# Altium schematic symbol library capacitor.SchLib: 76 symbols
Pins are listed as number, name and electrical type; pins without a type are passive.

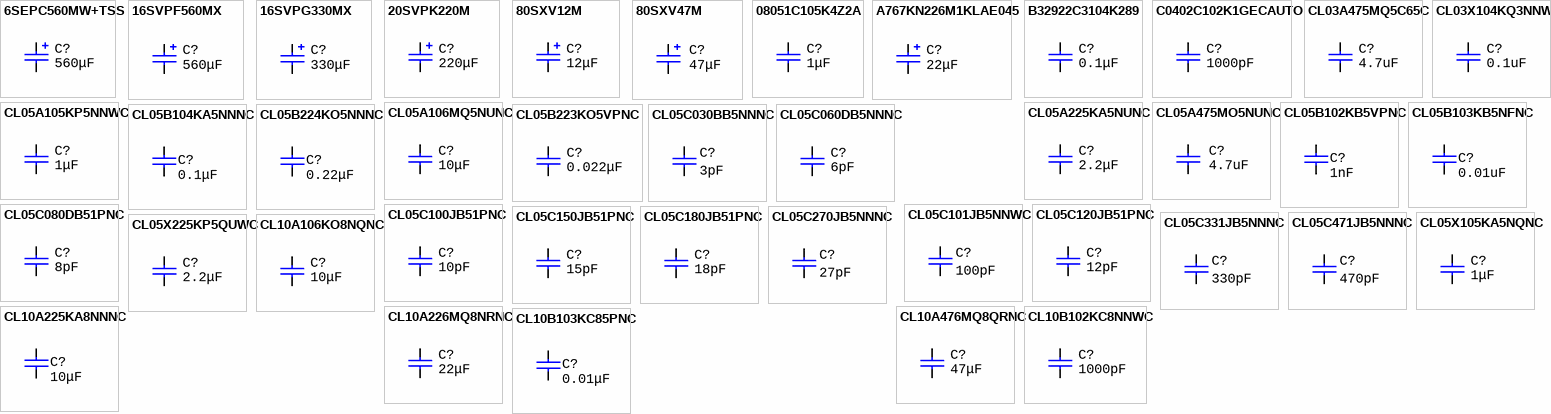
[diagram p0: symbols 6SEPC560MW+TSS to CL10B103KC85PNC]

## 6SEPC560MW+TSS
designator C?  value 560μF  (hidden comment: 6SEPC560MW+TSS)
560uF, 6.3V, D6.3C2.5H9, Polymer, ±20%, -55...+105°C; Manufacturer: Panasonic
footprint CAP: D6.3C2.5H9
pins: 1, 2

## 16SVPF560MX
designator C?  value 560μF  (hidden comment: 16SVPF560MX)
560uF, 16V, Polymer, ripple 3.9A, SMD D8AL10.5, ±20%, 18 mOhms, -55...+105°C; Manufacturer: Panasonic
footprint CAP: 16SVPF560MX (D8L10.5)
pins: 1, 2

## 16SVPG330MX
designator C?  value 330μF  (hidden comment: 16SVPG330MX)
330uF, 16V, Polymer, SMD D8AL6.9, ±20%, 16 mOhms, -55...+105°C; Manufacturer: Panasonic
footprint CAP: 16SVPG330MX
pins: 1, 2

## 20SVPK220M
designator C?  value 220μF  (hidden comment: 20SVPK220M)
220uF, 20V, Polymer, SMD D8AL6.9, ±20%, 25 mOhms, -55...+105°C; Manufacturer: Panasonic
footprint CAP: 16SVPG330MX
pins: 1, 2

## 80SXV12M
designator C?  value 12μF  (hidden comment: 80SXV12M)
12uF, 80V, Polymer, SMD D8AL6.9, ±20%, 60 mOhms, -55...+105°C; Manufacturer: Panasonic
footprint CAP: 16SVPG330MX
pins: 1, 2

## 80SXV47M
designator C?  value 47μF  (hidden comment: 80SXV47M)
47uF, 80V, 3.1A ripple, SMD D10A10.3H12.6C11, Polymer, ±20%, -55...+125°C; Manufacturer: Panasonic
footprint CAP: D10A10.3H12.6C11 (SMD Capacitor)
pins: 1, 2

## 08051C105K4Z2A
designator C?  value 1μF  (hidden comment: 08051C105K4Z2A)
1uF, 100V, 0805, X7R, ±10%, -55...+125°C; Manufacturer: Kyocera AVX
footprint CAP: 0805
pins: 1, 2

## A767KN226M1KLAE045
designator C?  value 22μF  (hidden comment: A767KN226M1KLAE045)
22uF, 80V, Polymer, ripple 2.1A, SMD D8AL10.5, ±20%, 45 mOhms, -55...+105°C; Manufacturer: Kemet
footprint CAP: 16SVPF560MX (D8L10.5)
pins: 1, 2

## B32922C3104K289
designator C?  value 0.1μF  (hidden comment: B32922C3104K289)
0.1uF, 630VDC, L18W5H15, Film, ±10%, -55...+125°C; Manufacturer: Epcos; Manufacturer: TDK EPCOS
footprint CAP: B32922 (18x5x15 mm)
pins: 1, 2

## C0402C102K1GECAUTO
designator C?  value 1000pF  (hidden comment: C0402C102K1GECAUTO)
1000pF, 100V, 0402, NPO, ±10%, -55...+125°C; Manufacturer: Kemet
footprint CAP: 0402
pins: 1, 2

## CL03A475MQ5C65C
designator C?  value 4.7uF  (hidden comment: CL03A475MQ5C65C)
4.7uF, 6.3V, 0201, X5R, ±20%, -55...+85°C; Manufacturer: Murata; Manufacturer: Samsung
footprint CAP: 0201
pins: 1, 2

## CL03X104KQ3NNWC
designator C?  value 0.1uF  (hidden comment: CL03X104KQ3NNWC)
0.1uF, 6.3V, 0201, X6S, ±20%, -55...+105°C; Manufacturer: Samsung
footprint CAP: 0201
pins: 1, 2

## CL05A105KP5NNWC
designator C?  value 1μF  (hidden comment: CL05A105KP5NNWC)
1uF, 10V, 0402, X5R, ±10%, -55...+125°C; Manufacturer: Samsung
footprint CAP: 0402
pins: 1, 2

## CL05A106MQ5NUNC
designator C?  value 10μF  (hidden comment: CL05A106MQ5NUNC)
10uF, 6.3V, 0402, X5R, ±10%, -55...+85°C; Manufacturer: Samsung
footprint CAP: 0402
pins: 1, 2

## CL05A225KA5NUNC
designator C?  value 2.2μF  (hidden comment: CL05A225KA5NUNC)
2.2uF, 25V, 0402, X5R, ±10%, -55...+85°C; Manufacturer: Samsung
footprint CAP: 0402
pins: 1, 2

## CL05A475MO5NUNC
designator C?  value 4.7uF  (hidden comment: CL05A475MO5NUNC)
4.7uF, 16V, 0402, X5R, ±20%, -55...+85°C; Manufacturer: Samsung
footprint CAP: 0402
pins: 1, 2

## CL05B102KB5VPNC
designator C?  value 1nF  (hidden comment: CL05B102KB5VPNC)
1nF, 50V, 0402, X7R, ±10%, -55...+125°C; Manufacturer: Samsung
footprint CAP: 0402
pins: 1, 2

## CL05B103KB5NFNC
designator C?  value 0.01uF  (hidden comment: CL05B103KB5NFNC)
0.01uF, 50V, 0402, X7R, ±10%, -55...+125°C; Manufacturer: Samsung
footprint CAP: 0402
pins: 1, 2

## CL05B104KA5NNNC
designator C?  value 0.1μF  (hidden comment: CL05B104KA5NNNC)
0.1uF, 25V, 0402, X7R, ±10%, -55...+125°C; Manufacturer: Samsung
footprint CAP: 0402
pins: 1, 2

## CL05B223KO5VPNC
designator C?  value 0.022μF  (hidden comment: CL05B223KO5VPNC)
0.022uF, 16V, 0402, X7R, ±10%, -55...+125°C; Manufacturer: Samsung
footprint CAP: 0402
pins: 1, 2

## CL05B224KO5NNNC
designator C?  value 0.22μF  (hidden comment: CL05B224KO5NNNC)
0.22uF, 16V, 0402, X7R, ±10%, -55...+125°C; Manufacturer: Samsung
footprint CAP: 0402
pins: 1, 2

## CL05C030BB5NNNC
designator C?  value 3pF  (hidden comment: CL05C030BB5NNNC)
3pF, 50V, 0402, NPO, ±5%, -55...+125°C; Manufacturer: Samsung
footprint CAP: 0402
pins: 1, 2

## CL05C060DB5NNNC
designator C?  value 6pF  (hidden comment: CL05C060DB5NNNC)
6pF, 50V, 0402, C0G (NP0), ±0.5pF, -55...+125°C; Manufacturer: Samsung
footprint CAP: 0402
pins: 1, 2

## CL05C080DB51PNC
designator C?  value 8pF  (hidden comment: CL05C080DB51PNC)
8pF, 50V, 0402, C0G (NP0), ±5%, -55...+125°C; Manufacturer: Samsung
footprint CAP: 0402
pins: 1, 2

## CL05C100JB51PNC
designator C?  value 10pF  (hidden comment: CL05C100JB51PNC)
10pF, 50V, 0402, C0G (NP0), ±5%, -55...+125°C; Manufacturer: Samsung
footprint CAP: 0402
pins: 1, 2

## CL05C101JB5NNWC
designator C?  value 100pF  (hidden comment: CL05C101JB5NNWC)
100pF, 50V, 0402, C0G (NP0), ±5%, -55...+125°C; Manufacturer: Samsung
footprint CAP: 0402
pins: 1, 2

## CL05C120JB51PNC
designator C?  value 12pF  (hidden comment: CL05C120JB51PNC)
12pF, 50V, 0402, C0G (NP0), ±5%, -55...+125°C; Manufacturer: Samsung
footprint CAP: 0402
pins: 1, 2

## CL05C150JB51PNC
designator C?  value 15pF  (hidden comment: CL05C150JB51PNC)
15pF, 50V, 0402, C0G (NP0), ±5%, -55...+125°C; Manufacturer: Samsung
footprint CAP: 0402
pins: 1, 2

## CL05C180JB51PNC
designator C?  value 18pF  (hidden comment: CL05C180JB51PNC)
18pF, 50V, 0402, C0G (NP0), ±5%, -55...+125°C; Manufacturer: Samsung
footprint CAP: 0402
pins: 1, 2

## CL05C270JB5NNNC
designator C?  value 27pF  (hidden comment: CL05C270JB5NNNC)
27pF, 50V, 0402, C0G (NP0), ±5%, -55...+125°C; Manufacturer: Samsung
footprint CAP: 0402
pins: 1, 2

## CL05C331JB5NNNC
designator C?  value 330pF  (hidden comment: CL05C331JB5NNNC)
330pF, 50V, 0402, NPO, ±5%, -55...+125°C; Manufacturer: Samsung
footprint CAP: 0402
pins: 1, 2

## CL05C471JB5NNNC
designator C?  value 470pF  (hidden comment: CL05C471JB5NNNC)
470pF, 50V, 0402, NPO, ±5%, -55...+125°C; Manufacturer: Samsung
footprint CAP: 0402
pins: 1, 2

## CL05X105KA5NQNC
designator C?  value 1μF  (hidden comment: CL05X105KA5NQNC)
1uF, 25V, 0402, X6S, ±10%, -55...+105°C; Manufacturer: Samsung
footprint CAP: 0402
pins: 1, 2

## CL05X225KP5QUWC
designator C?  value 2.2μF  (hidden comment: CL05X225KP5QUWC)
2.2uF, 10V, 0402, X6S, ±10%, -55...+85°C; Manufacturer: Samsung
footprint CAP: 0402
pins: 1, 2

## CL10A106KO8NQNC
designator C?  value 10μF  (hidden comment: CL10A106KO8NQNC)
10uF, 16V, 0603, X7R, ±10%, -55...+85°C; Manufacturer: Samsung
footprint CAP: 0603
pins: 1, 2

## CL10A225KA8NNNC
designator C?  value 10μF  (hidden comment: CL10A225KA8NNNC)
10uF, 25V, 0603, X5R, ±10%, -55...+85°C; Manufacturer: Samsung
footprint CAP: 0603
pins: 1, 2

## CL10A226MQ8NRNC
designator C?  value 22μF  (hidden comment: CL10A226MQ8NRNC)
22uF, 6.3V, 0603, X7R, ±20%, -55...+85°C; Manufacturer: Samsung
footprint CAP: 0603
pins: 1, 2

## CL10A476MQ8QRNC
designator C?  value 47μF  (hidden comment: CL10A476MQ8QRNC)
47uF, 6.3V, 0603, X5R, ±20%, -55...+85°C; Manufacturer: Samsung
footprint CAP: 0603
pins: 1, 2

## CL10B102KC8NNWC
designator C?  value 1000pF  (hidden comment: CL10B102KC8NNWC)
1000pF, 100V, 0603, NPO, ±10%, -55...+125°C; Manufacturer: Samsung
footprint CAP: 0603
pins: 1, 2

## CL10B103KC85PNC
designator C?  value 0.01μF  (hidden comment: CL10B103KC85PNC)
0.01uF, 100V, 0603, X7R, ±10%, -55...+125°C; Manufacturer: Samsung
footprint CAP: 0603
pins: 1, 2

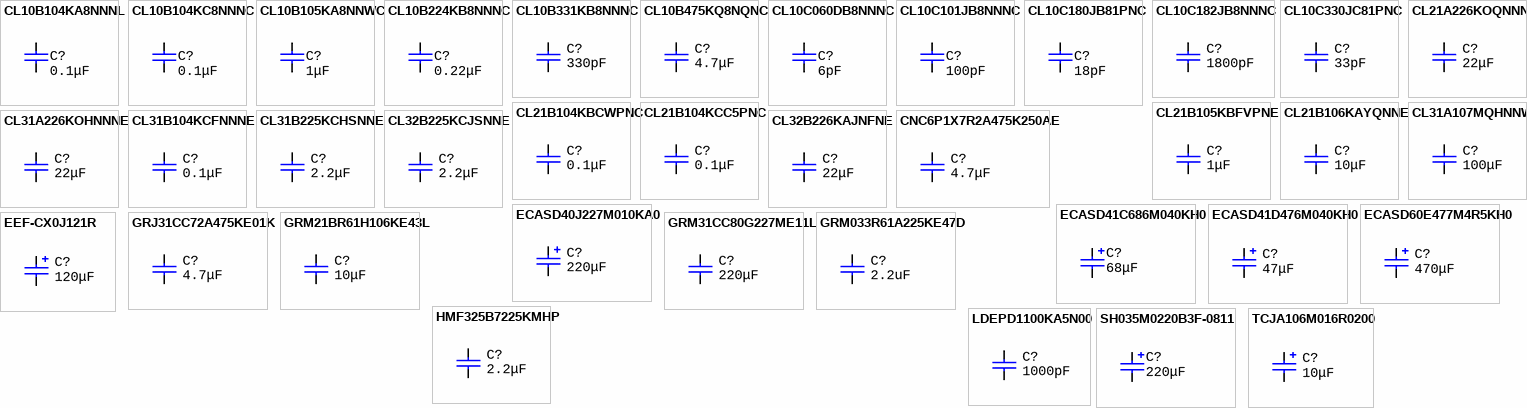
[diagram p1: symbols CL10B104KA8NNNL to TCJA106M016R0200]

## CL10B104KA8NNNL
designator C?  value 0.1μF  (hidden comment: CL10B104KA8NNNL)
0.1uF, 25V, 0603, X7R, ±10%, -55...+125°C; Manufacturer: Samsung
footprint CAP: 0603
pins: 1, 2

## CL10B104KC8NNNC
designator C?  value 0.1μF  (hidden comment: CL10B104KC8NNNC)
0.1uF, 100V, 0603, X7R, ±10%, -55...+125°C; Manufacturer: Samsung
footprint CAP: 0603
pins: 1, 2

## CL10B105KA8NNWC
designator C?  value 1μF  (hidden comment: CL10B105KA8NNWC)
1uF, 25V, 0603, X7R, ±10%, -55...+125°C; Manufacturer: Samsung
footprint CAP: 0603
pins: 1, 2

## CL10B224KB8NNNC
designator C?  value 0.22μF  (hidden comment: CL10B224KB8NNNC)
0.22uF, 50V, 0603, X7R, ±10%, -55...+125°C; Manufacturer: Samsung
footprint CAP: 0603
pins: 1, 2

## CL10B331KB8NNNC
designator C?  value 330pF  (hidden comment: CL10B331KB8NNNC)
330pF, 50V, 0603, X7R, ±10%, -55...+125°C; Manufacturer: Samsung
footprint CAP: 0603
pins: 1, 2

## CL10B475KQ8NQNC
designator C?  value 4.7μF  (hidden comment: CL10B475KQ8NQNC)
4.7uF, 6.3V, 0603, X7R, ±20%, -55...+85°C; Manufacturer: Samsung
footprint CAP: 0603
pins: 1, 2

## CL10C060DB8NNNC
designator C?  value 6pF  (hidden comment: CL10C060DB8NNNC)
6pF, 50V, 0603, C0G (NP0), ±10%, -55...+125°C; Manufacturer: Samsung
footprint CAP: 0603
pins: 1, 2

## CL10C101JB8NNNC
designator C?  value 100pF  (hidden comment: CL10C101JB8NNNC)
100pF, 50V, 0603, C0G (NP0), ±5%, -55...+125°C; Manufacturer: Samsung
footprint CAP: 0603
pins: 1, 2

## CL10C180JB81PNC
designator C?  value 18pF  (hidden comment: CL10C180JB81PNC)
18pF, 50V, 0603, C0G (NP0), ±5%, -55...+125°C; Manufacturer: Samsung
footprint CAP: 0603
pins: 1, 2

## CL10C182JB8NNNC
designator C?  value 1800pF  (hidden comment: CL10C182JB8NNNC)
1800pF, 50V, 0603, NPO, ±10%, -55...+125°C; Manufacturer: Samsung
footprint CAP: 0603
pins: 1, 2

## CL10C330JC81PNC
designator C?  value 33pF  (hidden comment: CL10C330JC81PNC)
33pF, 100V, 0603, NPO, ±10%, -55...+125°C; Manufacturer: Samsung
footprint CAP: 0603
pins: 1, 2

## CL21A226KOQNNNE
designator C?  value 22μF  (hidden comment: CL21A226KOQNNNE)
22uF, 16V, 0805, X7R, ±10%, -55...+125°C; Manufacturer: Samsung
footprint CAP: 0805
pins: 1, 2

## CL21B104KBCWPNC
designator C?  value 0.1μF  (hidden comment: CL21B104KBCWPNC)
0.1uF, 50V, 0805, X7R, ±10%, -55...+125°C; Manufacturer: Samsung
footprint CAP: 0805
pins: 1, 2

## CL21B104KCC5PNC
designator C?  value 0.1μF  (hidden comment: CL21B104KCC5PNC)
0.1uF, 100V, 0805, X7R, ±10%, -55...+125°C; Manufacturer: Samsung
footprint CAP: 0805
pins: 1, 2

## CL21B105KBFVPNE
designator C?  value 1μF  (hidden comment: CL21B105KBFVPNE)
1uF, 50V, 0805, X7R, ±10%, -55...+125°C; Manufacturer: Samsung
footprint CAP: 0805
pins: 1, 2

## CL21B106KAYQNNE
designator C?  value 10μF  (hidden comment: CL21B106KAYQNNE)
10uF, 25V, 0805, X7R, ±10%, -55...+125°C; Manufacturer: Samsung
footprint CAP: 0805
pins: 1, 2

## CL31A107MQHNNWE
designator C?  value 100μF  (hidden comment: CL31A107MQHNNWE)
100uF, 6.3V, 1206, X5R, ±20%, -55...+125°C; Manufacturer: Samsung
footprint CAP: 1206
pins: 1, 2

## CL31A226KOHNNNE
designator C?  value 22μF  (hidden comment: CL31A226KOHNNNE)
22uF, 16V, 1206, X5R, ±10%, -55...+125°C; Manufacturer: Samsung
footprint CAP: 1206
pins: 1, 2

## CL31B104KCFNNNE
designator C?  value 0.1μF  (hidden comment: CL31B104KCFNNNE)
0.1uF, 100V, 1206, X7R, ±10%, -55...+125°C; Manufacturer: Samsung
footprint CAP: 1206
pins: 1, 2

## CL31B225KCHSNNE
designator C?  value 2.2μF  (hidden comment: CL31B225KCHSNNE)
2.2uF, 100V, 1206, X7R, ±10%, -55...+125°C; Manufacturer: Samsung
footprint CAP: 1206
pins: 1, 2

## CL32B225KCJSNNE
designator C?  value 2.2μF  (hidden comment: CL32B225KCJSNNE)
2.2uF, 100V, 1210, X7R, ±10%, -55...+125°C; Manufacturer: Samsung
footprint CAP: 1210
pins: 1, 2

## CL32B226KAJNFNE
designator C?  value 22μF  (hidden comment: CL32B226KAJNFNE)
22uF, 25V, 1210, X5R, ±10%, -55...+125°C; PartNumber: CL32B105KCJSNNE; Manufacturer: Samsung
footprint CAP: 1210
pins: 1, 2

## CNC6P1X7R2A475K250AE
designator C?  value 4.7μF  (hidden comment: CNC6P1X7R2A475K250AE)
4.7uF, 100V, 1210, X7R, ±10%, -55...+125°C; Manufacturer: Samsung; Manufacturer: TDK
footprint CAP: 1210
pins: 1, 2

## ECASD40J227M010KA0
designator C?  value 220μF  (hidden comment: ECASD40J227M010KA0)
220uF, 6.3V, Type E (7343), ±10%, 10 mOhms, -55...+125°C; Manufacturer: Murata
footprint CAP: TANTAL-E (7343)
pins: 1, 2

## ECASD41C686M040KH0
designator C?  value 68μF  (hidden comment: ECASD41C686M040KH0)
68uF, 16V, Type E (7343), ±20%, 40 mOhms, -55...+125°C; Manufacturer: Murata; Manufacturer Part Number: ECASD41C685M070K00
footprint CAP: TANTAL-E (7343)
pins: 1, 2

## ECASD41D476M040KH0
designator C?  value 47μF  (hidden comment: ECASD41D476M040KH0)
47uF, 25V, Type E (7343), ±20%, 40 mOhms, -55...+125°C; Manufacturer: Murata
footprint CAP: TANTAL-E (7343)
pins: 1, 2

## ECASD60E477M4R5KH0
designator C?  value 470μF  (hidden comment: ECASD60E477M4R5KH0)
470uF, 2.5V, Type E (7343), ±20%, 4.5 mOhms, -55...+125°C; Manufacturer: Murata
footprint CAP: TANTAL-E (7343)
pins: 1, 2

## EEF-CX0J121R
designator C?  value 120μF  (hidden comment: EEF-CX0J121R)
120uF, 6.3V, Type D (7343), ±20%, -55...+175°C; Manufacturer: KEMET; Manufacturer: Panasonic
footprint CAP: TANTAL-E (7343)
pins: 1, 2

## GRJ31CC72A475KE01K
designator C?  value 4.7μF  (hidden comment: GRJ31CC72A475KE01K)
4.7uF, 100V, 1206, X7S, ±10%, -55...+125°C; Manufacturer: Murata
footprint CAP: 1206
pins: 1, 2

## GRM21BR61H106KE43L
designator C?  value 10μF  (hidden comment: GRM21BR61H106KE43L)
10uF, 50V, 0805, X5R, ±10%, -55...+125°C; Manufacturer: Murata
footprint CAP: 0805
pins: 1, 2

## GRM31CC80G227ME11L
designator C?  value 220μF  (hidden comment: GRM31CC80G227ME11L)
220uF, 4V, 1206, X6S, ±20%, -55...+125°C; Manufacturer: Murata
footprint CAP: 1206
pins: 1, 2

## GRM033R61A225KE47D
designator C?  value 2.2uF  (hidden comment: GRM033R61A225KE47D)
2.2uF, 10V, 0201, X5R, ±20%, -55...+85°C; Manufacturer: Murata
footprint CAP: 0201
pins: 1, 2

## HMF325B7225KMHP
designator C?  value 2.2μF  (hidden comment: HMF325B7225KMHP)
2.2uF, 100V, 1210, X5R, ±10%, -55...+125°C; Manufacturer: Taiyo Yuden
footprint CAP: 1210
pins: 1, 2

## LDEPD1100KA5N00
designator C?  value 1000pF  (hidden comment: LDEPD1100KA5N00)
1000pF, 630VDC, 2220, Film, ±10%, -55...+125°C; Manufacturer: KEMET
footprint CAP: 2220
pins: 1, 2

## SH035M0220B3F-0811
designator C?  value 220μF  (hidden comment: SH035M0220B3F-0811)
220uF, 35V, D8C3.5H11, Electrolytic, ±20%, 2000 hrs, -40...+105°C; Manufacturer: YAGEO
footprint CAP: D8C3.5H11
pins: 1, 2

## TCJA106M016R0200
designator C?  value 10μF  (hidden comment: TCJA106M016R0200)
10uF, 16V, Type A (3216), ±20%, 200 mOhms, -55...+125°C; Manufacturer: AVX; Manufacturer: Kyocera AVX
footprint CAP: TANTAL-A (3216)
pins: 1, 2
